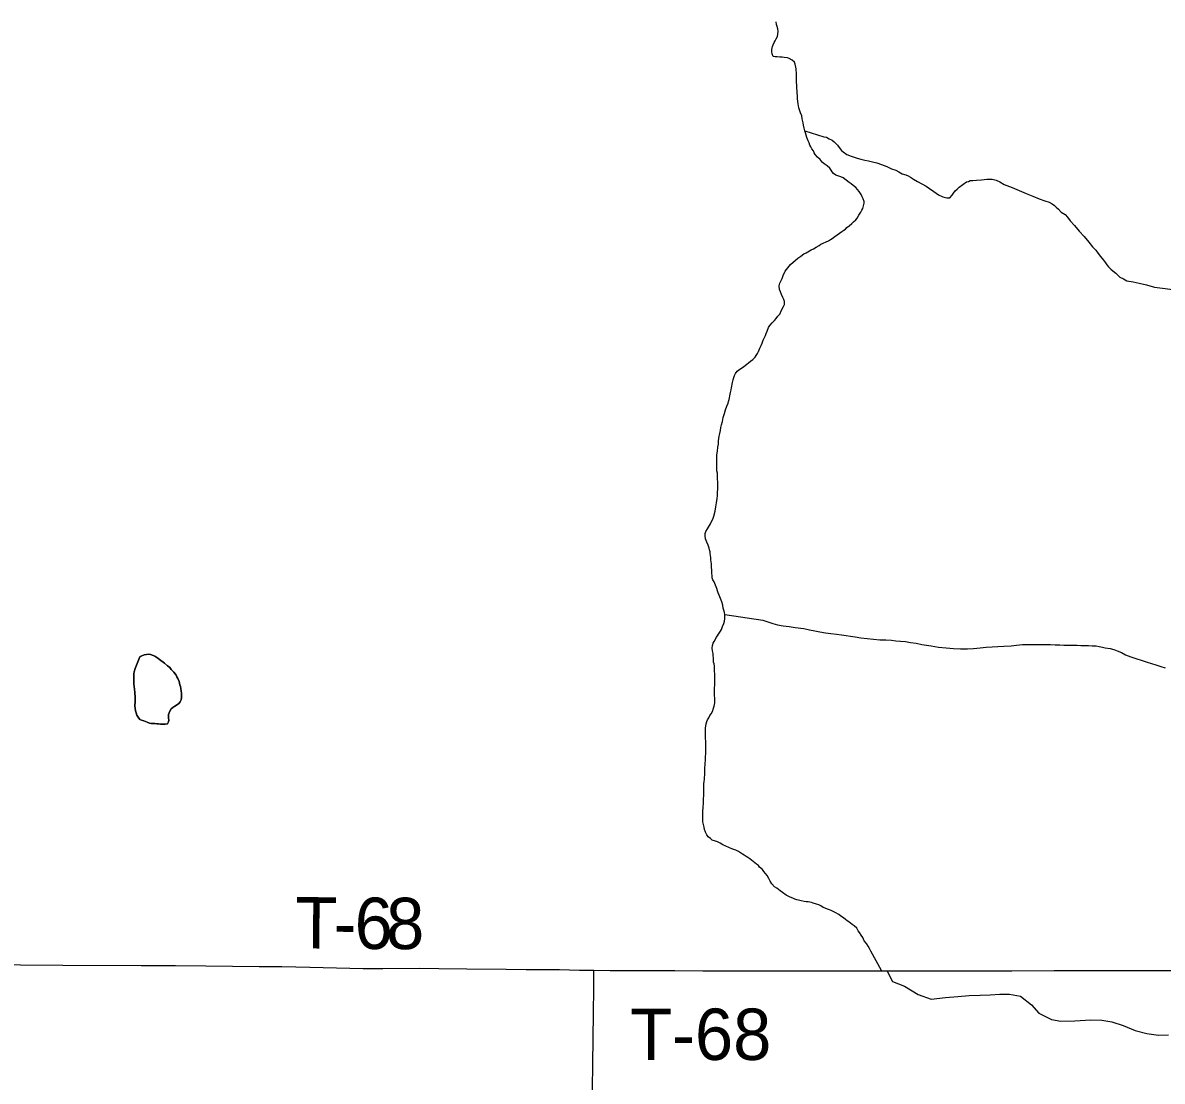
# Model space of a CAD drawing. Extents: x -17 to 88, y -5 to 22.
# Drawn here: x -14.14 to -12.88, y 15.1 to 16.271 of the extents above; entities that cross this region are included whole.
import ezdxf

# ---------------------------------------------------------------- set-up
doc = ezdxf.new("R2010")
doc.units = 0
for name, color, linetype in [('GM_X_City_Street', 7, 'Continuous'), ('GM_X_Minor_Lake', 7, 'Continuous'), ('GM_X_Minor_River', 7, 'Continuous'), ('GM_X_Township_Road', 7, 'Continuous'), ('GM_X_Township_Road_Text', 7, 'Continuous')]:
    doc.layers.add(name, color=color, linetype=linetype)

msp = doc.modelspace()

# ---------------------------------------------------------------- linework, layer by layer
at = {"layer": 'GM_X_City_Street'}
msp.add_lwpolyline([(-14.2652, 15.2295), (-14.2503, 15.2295), (-14.1428, 15.2288), (-14.0962, 15.2284), (-14.0095, 15.2281), (-13.9715, 15.2279), (-13.9378, 15.2277), (-13.8787, 15.227), (-13.8539, 15.2268), (-13.8228, 15.2264), (-13.7638, 15.2248), (-13.7421, 15.2248), (-13.7017, 15.2252), (-13.6799, 15.2248), (-13.6489, 15.2243), (-13.6054, 15.2239), (-13.5836, 15.2237), (-13.5464, 15.2235), (-13.5246, 15.223), (-13.5086, 15.2228)], dxfattribs=at)
at = {"layer": 'GM_X_Minor_Lake'}
for points in [[(-14.0108, 15.5694), (-14.0104, 15.5698), (-14.0093, 15.5702), (-14.0059, 15.5717), (-14.0036, 15.5721), (-14.0009, 15.5725), (-13.999, 15.5721), (-13.996, 15.571), (-13.9941, 15.5702), (-13.9911, 15.5679), (-13.9892, 15.5664), (-13.9835, 15.5626), (-13.9804, 15.5596), (-13.9778, 15.5577), (-13.9763, 15.5554), (-13.9732, 15.5524), (-13.9706, 15.5493), (-13.9698, 15.5474), (-13.9687, 15.5455), (-13.9675, 15.5421), (-13.9668, 15.5387), (-13.966, 15.5368), (-13.9656, 15.5345), (-13.9653, 15.5315), (-13.9649, 15.5292), (-13.9649, 15.5269), (-13.9649, 15.5246), (-13.9653, 15.522), (-13.9664, 15.5197), (-13.9679, 15.5178), (-13.9702, 15.5159), (-13.9721, 15.5151), (-13.9744, 15.5136), (-13.9763, 15.5121), (-13.9778, 15.5094), (-13.9793, 15.5056), (-13.9793, 15.5037), (-13.9793, 15.5015), (-13.9789, 15.4996), (-13.9793, 15.4977), (-13.9804, 15.4954), (-13.9827, 15.495), (-13.9857, 15.495), (-13.988, 15.495), (-13.9903, 15.4954), (-13.9922, 15.4954), (-13.9941, 15.4958), (-13.9964, 15.4958), (-13.9983, 15.4958), (-14.0002, 15.4961), (-14.0028, 15.4973), (-14.0047, 15.498), (-14.0066, 15.4988), (-14.0089, 15.4996), (-14.0108, 15.5003), (-14.0127, 15.5026), (-14.0142, 15.5049), (-14.015, 15.5075), (-14.0157, 15.5098), (-14.0161, 15.5129), (-14.0165, 15.5148), (-14.0161, 15.5204), (-14.0161, 15.5223), (-14.0161, 15.5242), (-14.0161, 15.5265), (-14.0165, 15.5284), (-14.0165, 15.5303), (-14.0169, 15.5334), (-14.0172, 15.5372), (-14.0176, 15.5394), (-14.0176, 15.5417), (-14.0176, 15.5444), (-14.0176, 15.5467), (-14.0176, 15.5489), (-14.0176, 15.5508), (-14.0173, 15.5531), (-14.0161, 15.5565), (-14.0154, 15.5584), (-14.0108, 15.5694)], [(-14.0108, 15.5694), (-14.0154, 15.5584), (-14.0161, 15.5565), (-14.0173, 15.5531), (-14.0176, 15.5508), (-14.0176, 15.5489), (-14.0176, 15.5467), (-14.0176, 15.5444), (-14.0176, 15.5417), (-14.0176, 15.5394), (-14.0172, 15.5372), (-14.0169, 15.5334), (-14.0165, 15.5303), (-14.0165, 15.5284), (-14.0161, 15.5265), (-14.0161, 15.5242), (-14.0161, 15.5223), (-14.0161, 15.5204), (-14.0165, 15.5148), (-14.0161, 15.5129), (-14.0157, 15.5098), (-14.015, 15.5075), (-14.0142, 15.5049), (-14.0127, 15.5026), (-14.0108, 15.5003), (-14.0089, 15.4996), (-14.0066, 15.4988), (-14.0047, 15.498), (-14.0028, 15.4973), (-14.0002, 15.4961), (-13.9983, 15.4958), (-13.9964, 15.4958), (-13.9941, 15.4958), (-13.9922, 15.4954), (-13.9903, 15.4954), (-13.988, 15.495), (-13.9857, 15.495), (-13.9827, 15.495), (-13.9804, 15.4954), (-13.9793, 15.4977)], [(-13.9793, 15.4977), (-13.9789, 15.4996), (-13.9793, 15.5015), (-13.9793, 15.5037), (-13.9793, 15.5056), (-13.9778, 15.5094), (-13.9763, 15.5121), (-13.9744, 15.5136), (-13.9721, 15.5151), (-13.9702, 15.5159), (-13.9679, 15.5178), (-13.9664, 15.5197), (-13.9653, 15.522), (-13.9649, 15.5246), (-13.9649, 15.5269), (-13.9649, 15.5292), (-13.9653, 15.5315), (-13.9656, 15.5345), (-13.966, 15.5368), (-13.9668, 15.5387), (-13.9675, 15.5421), (-13.9687, 15.5455), (-13.9698, 15.5474), (-13.9706, 15.5493), (-13.9732, 15.5524), (-13.9763, 15.5554), (-13.9778, 15.5577), (-13.9804, 15.5596), (-13.9835, 15.5626), (-13.9892, 15.5664), (-13.9911, 15.5679), (-13.9941, 15.5702), (-13.996, 15.571), (-13.999, 15.5721), (-14.0009, 15.5725), (-14.0036, 15.5721), (-14.0059, 15.5717), (-14.0093, 15.5702), (-14.0104, 15.5698), (-14.0108, 15.5694)]]:
    msp.add_lwpolyline(points, dxfattribs=at)
at = {"layer": 'GM_X_Minor_River'}
for points in [[(-13.2942, 16.2322), (-13.298, 16.2326), (-13.3003, 16.2329), (-13.3029, 16.2329), (-13.3056, 16.2333), (-13.3079, 16.2333), (-13.3101, 16.2337), (-13.3113, 16.2364), (-13.3117, 16.2386), (-13.3117, 16.2413), (-13.3109, 16.2447), (-13.3102, 16.2466), (-13.309, 16.2489), (-13.3079, 16.2508), (-13.3067, 16.2531), (-13.3052, 16.2557), (-13.3045, 16.2614), (-13.3048, 16.2641), (-13.3056, 16.2667), (-13.3064, 16.269), (-13.3067, 16.2721)], [(-13.2991, 15.9914), (-13.2968, 15.996), (-13.2941, 15.9998), (-13.2911, 16.0036), (-13.2881, 16.0062), (-13.2858, 16.0078), (-13.2828, 16.0104), (-13.2797, 16.0127), (-13.2763, 16.0154), (-13.2737, 16.0165), (-13.2718, 16.0176), (-13.2699, 16.0188), (-13.268, 16.0199), (-13.2657, 16.0207), (-13.2627, 16.0226), (-13.2592, 16.0245), (-13.2573, 16.026), (-13.249, 16.0298), (-13.2467, 16.0313), (-13.2448, 16.0321), (-13.2418, 16.0343), (-13.2395, 16.0362), (-13.2369, 16.0381), (-13.2342, 16.04), (-13.2319, 16.0416), (-13.23, 16.0427), (-13.2285, 16.0446), (-13.2262, 16.0461), (-13.2232, 16.0488), (-13.2213, 16.0507), (-13.2186, 16.053), (-13.2171, 16.0549), (-13.2152, 16.0579), (-13.213, 16.0613), (-13.2122, 16.0636), (-13.2111, 16.0655), (-13.2103, 16.0685), (-13.2095, 16.0712), (-13.2095, 16.0731), (-13.2107, 16.0761), (-13.2118, 16.0784), (-13.2126, 16.0811), (-13.2149, 16.0841), (-13.2168, 16.0864), (-13.2187, 16.0887), (-13.2217, 16.0909), (-13.224, 16.0928), (-13.2262, 16.0944), (-13.2327, 16.0993), (-13.2354, 16.1004), (-13.2376, 16.1012), (-13.2407, 16.1023), (-13.2433, 16.1042), (-13.2448, 16.1061), (-13.246, 16.108), (-13.2475, 16.1099), (-13.2505, 16.1126), (-13.2536, 16.1149), (-13.2559, 16.1168), (-13.2581, 16.1198), (-13.2612, 16.1224), (-13.2638, 16.1251), (-13.2646, 16.127), (-13.2657, 16.1293), (-13.2672, 16.1316), (-13.2684, 16.1335), (-13.2695, 16.1354), (-13.2703, 16.138), (-13.2714, 16.1403), (-13.2722, 16.1422), (-13.2729, 16.1441), (-13.2737, 16.1467), (-13.2745, 16.149), (-13.2752, 16.1513), (-13.276, 16.1543), (-13.2767, 16.1578), (-13.2771, 16.1604), (-13.2779, 16.1646), (-13.2786, 16.168), (-13.2798, 16.1714), (-13.2809, 16.1745), (-13.2817, 16.1767), (-13.2821, 16.179), (-13.2824, 16.1813), (-13.2828, 16.184), (-13.2832, 16.187), (-13.2832, 16.1897), (-13.2836, 16.1938), (-13.2843, 16.2067), (-13.2843, 16.2094), (-13.2843, 16.2121), (-13.2843, 16.214), (-13.2843, 16.2159), (-13.2847, 16.2181), (-13.2847, 16.22), (-13.2851, 16.2219), (-13.2859, 16.225), (-13.2866, 16.2272), (-13.2893, 16.2295), (-13.2923, 16.2314), (-13.2942, 16.2322)], [(-13.2752, 16.1513), (-13.254, 16.1449), (-13.2513, 16.1445), (-13.2483, 16.1426), (-13.2449, 16.1411), (-13.2426, 16.1392), (-13.2407, 16.1373), (-13.2388, 16.1354), (-13.2361, 16.1316), (-13.2346, 16.1297), (-13.2327, 16.1281), (-13.2285, 16.1251), (-13.224, 16.1232), (-13.2171, 16.1213), (-13.213, 16.1202), (-13.2088, 16.119), (-13.2046, 16.1183), (-13.2001, 16.1171), (-13.1955, 16.116), (-13.1902, 16.1141), (-13.1845, 16.1118), (-13.1792, 16.1095), (-13.1746, 16.108), (-13.1712, 16.1061), (-13.1674, 16.1039), (-13.1633, 16.1027), (-13.1606, 16.1016), (-13.1583, 16.1001), (-13.1549, 16.0978), (-13.1504, 16.0955), (-13.1458, 16.0928), (-13.1409, 16.0902), (-13.1371, 16.0875), (-13.1325, 16.0841), (-13.1272, 16.0807), (-13.1223, 16.0784), (-13.1181, 16.0773), (-13.1147, 16.0773), (-13.112, 16.0803), (-13.1105, 16.0826), (-13.1086, 16.0849), (-13.1067, 16.0868), (-13.1044, 16.0891), (-13.0961, 16.0948), (-13.0942, 16.0955), (-13.0923, 16.0963), (-13.0893, 16.0963), (-13.0851, 16.0967), (-13.0798, 16.097), (-13.0737, 16.0978), (-13.068, 16.0978), (-13.0635, 16.0967), (-13.0593, 16.0948), (-13.0544, 16.0921), (-13.0456, 16.0887), (-13.038, 16.0853), (-13.0304, 16.0822), (-13.0229, 16.0792), (-13.016, 16.0762), (-13.0096, 16.0739), (-13.0046, 16.0724), (-13.0016, 16.0705), (-12.9989, 16.0689), (-12.997, 16.067), (-12.9944, 16.0648), (-12.9914, 16.0614), (-12.9872, 16.0587), (-12.9845, 16.056), (-12.9815, 16.0519), (-12.9769, 16.0465), (-12.9716, 16.0405), (-12.9659, 16.0344), (-12.961, 16.0283), (-12.9568, 16.023), (-12.953, 16.0192), (-12.9504, 16.0158), (-12.9481, 16.0124), (-12.9447, 16.0082), (-12.9424, 16.0055), (-12.9409, 16.0033), (-12.939, 16.001), (-12.9367, 15.9983), (-12.9344, 15.9964), (-12.931, 15.9938), (-12.9291, 15.9919), (-12.9265, 15.9896), (-12.9227, 15.9877), (-12.9189, 15.9854), (-12.912, 15.9843), (-12.9052, 15.9828), (-12.8972, 15.9809), (-12.8881, 15.9786), (-12.8619, 15.9752)], [(-13.3844, 15.6983), (-13.3851, 15.7002), (-13.3855, 15.7032), (-13.3855, 15.7059), (-13.3848, 15.7081), (-13.3829, 15.7112), (-13.3817, 15.7131), (-13.3794, 15.7165), (-13.3783, 15.7191), (-13.3768, 15.7218), (-13.3757, 15.7252), (-13.3745, 15.7305), (-13.3734, 15.7355), (-13.373, 15.74), (-13.3722, 15.7446), (-13.3719, 15.7476), (-13.3719, 15.7495), (-13.3719, 15.7522), (-13.3715, 15.7545), (-13.3715, 15.7575), (-13.3715, 15.7605), (-13.3715, 15.7632), (-13.3719, 15.7662), (-13.3719, 15.77), (-13.3719, 15.7727), (-13.3723, 15.7753), (-13.3723, 15.778), (-13.3723, 15.7883), (-13.3723, 15.7928), (-13.3719, 15.797), (-13.3715, 15.8015), (-13.3707, 15.8046), (-13.3707, 15.8084), (-13.3704, 15.811), (-13.37, 15.8137), (-13.3692, 15.8167), (-13.3685, 15.8198), (-13.3681, 15.8232), (-13.3673, 15.8262), (-13.3662, 15.83), (-13.3654, 15.8342), (-13.3639, 15.8388), (-13.3628, 15.8429), (-13.3613, 15.8467), (-13.3601, 15.8502), (-13.3594, 15.8521), (-13.359, 15.854), (-13.3586, 15.8562), (-13.3582, 15.8581), (-13.3579, 15.86), (-13.3575, 15.8619), (-13.3567, 15.865), (-13.3563, 15.8669), (-13.356, 15.8688), (-13.3556, 15.871), (-13.3552, 15.8729), (-13.3544, 15.876), (-13.3537, 15.8786), (-13.3529, 15.8809), (-13.3518, 15.8828), (-13.3499, 15.8855), (-13.3472, 15.8878), (-13.3453, 15.8889), (-13.3427, 15.8908), (-13.3393, 15.8931), (-13.3374, 15.8946), (-13.3351, 15.8965), (-13.3328, 15.8984), (-13.3302, 15.901), (-13.329, 15.9029), (-13.3275, 15.9052), (-13.3264, 15.9071), (-13.3249, 15.9109), (-13.3233, 15.914), (-13.3222, 15.9166), (-13.3211, 15.9197), (-13.3199, 15.9227), (-13.3188, 15.925), (-13.318, 15.9273), (-13.3169, 15.9299), (-13.3154, 15.9337), (-13.3139, 15.936), (-13.3112, 15.939), (-13.3085, 15.9417), (-13.307, 15.9436), (-13.3048, 15.9462), (-13.3029, 15.9485), (-13.301, 15.9531), (-13.2987, 15.9569), (-13.2975, 15.9592), (-13.2975, 15.9626), (-13.2983, 15.9648), (-13.2994, 15.9671), (-13.301, 15.9705), (-13.3021, 15.9732), (-13.3032, 15.9759), (-13.3036, 15.98), (-13.3029, 15.9827), (-13.3017, 15.985), (-13.3002, 15.988), (-13.2991, 15.9914)], [(-13.387, 15.4157), (-13.387, 15.4195), (-13.387, 15.4233), (-13.387, 15.4271), (-13.387, 15.429), (-13.3866, 15.4317), (-13.3862, 15.434), (-13.3862, 15.4362), (-13.3858, 15.4389), (-13.3858, 15.4419), (-13.3858, 15.4461), (-13.3854, 15.451), (-13.3851, 15.4556), (-13.3851, 15.4594), (-13.3847, 15.4621), (-13.3847, 15.4681), (-13.3847, 15.47), (-13.3847, 15.4719), (-13.3847, 15.4742), (-13.3847, 15.4761), (-13.3851, 15.4792), (-13.3851, 15.4822), (-13.3851, 15.486), (-13.3851, 15.489), (-13.3851, 15.4909), (-13.3847, 15.4928), (-13.3843, 15.4955), (-13.3836, 15.4978), (-13.3828, 15.5), (-13.3813, 15.5019), (-13.3801, 15.5046), (-13.3786, 15.5065), (-13.3771, 15.5092), (-13.376, 15.5129), (-13.3756, 15.5148), (-13.3752, 15.5167), (-13.3748, 15.5186), (-13.3748, 15.5236), (-13.3752, 15.527), (-13.3752, 15.5308), (-13.3752, 15.5346), (-13.3748, 15.5388), (-13.3748, 15.5422), (-13.3748, 15.546), (-13.3748, 15.5483), (-13.3748, 15.5502), (-13.3752, 15.554), (-13.3752, 15.5566), (-13.3752, 15.5593), (-13.3756, 15.5619), (-13.376, 15.5638), (-13.376, 15.568), (-13.3764, 15.571), (-13.3767, 15.5733), (-13.3771, 15.576), (-13.3775, 15.579), (-13.3771, 15.5821), (-13.3764, 15.5847), (-13.3756, 15.5866), (-13.3741, 15.5889), (-13.3733, 15.5908), (-13.3718, 15.5927), (-13.3707, 15.5946), (-13.3684, 15.598), (-13.3673, 15.5999), (-13.3661, 15.6029), (-13.3646, 15.6064), (-13.3639, 15.609), (-13.3635, 15.6117), (-13.3635, 15.614), (-13.3635, 15.6162), (-13.3639, 15.6185), (-13.3646, 15.6212), (-13.3654, 15.6235), (-13.3658, 15.6265), (-13.3669, 15.6303), (-13.3684, 15.6341), (-13.3699, 15.6379), (-13.3711, 15.6402), (-13.3718, 15.6424), (-13.3726, 15.6451), (-13.3741, 15.6489), (-13.3756, 15.6523), (-13.3768, 15.6546), (-13.3775, 15.6569), (-13.3779, 15.6641), (-13.3779, 15.666), (-13.3783, 15.6679), (-13.3783, 15.6702), (-13.3783, 15.6724), (-13.3787, 15.6747), (-13.3791, 15.677), (-13.3791, 15.6793), (-13.3794, 15.6816), (-13.3798, 15.6838), (-13.3798, 15.6857), (-13.3806, 15.688), (-13.381, 15.6899), (-13.3821, 15.6929), (-13.3836, 15.6964), (-13.3844, 15.6983)], [(-13.3635, 15.6162), (-13.3214, 15.6102), (-13.316, 15.6083), (-13.3107, 15.6064), (-13.3054, 15.6049), (-13.299, 15.6037), (-13.2925, 15.603), (-13.2857, 15.6018), (-13.2762, 15.6007), (-13.2698, 15.5995), (-13.2641, 15.5984), (-13.2584, 15.5973), (-13.2523, 15.5961), (-13.2462, 15.5954), (-13.2402, 15.5946), (-13.2345, 15.5939), (-13.2295, 15.5931), (-13.2246, 15.5923), (-13.2193, 15.5916), (-13.2132, 15.5904), (-13.192, 15.5885), (-13.1855, 15.5885), (-13.1794, 15.5878), (-13.1745, 15.5874), (-13.1692, 15.5867), (-13.1639, 15.5863), (-13.1582, 15.5855), (-13.1521, 15.5848), (-13.1457, 15.5832), (-13.1354, 15.5817), (-13.1271, 15.5802), (-13.1187, 15.5794), (-13.1108, 15.5787), (-13.1028, 15.5783), (-13.0952, 15.5783), (-13.0884, 15.5787), (-13.0812, 15.5794), (-13.0743, 15.5802), (-13.0679, 15.5806), (-13.0614, 15.581), (-13.055, 15.5814), (-13.047, 15.5817), (-13.0409, 15.5825), (-13.0341, 15.5833), (-13.0277, 15.5833), (-13.0212, 15.5833), (-13.0151, 15.5833), (-13.0091, 15.5833), (-13.0034, 15.5833), (-12.9981, 15.5829), (-12.9931, 15.5829), (-12.9886, 15.5825), (-12.984, 15.5825), (-12.981, 15.5825), (-12.9776, 15.5825), (-12.9738, 15.5825), (-12.9696, 15.5821), (-12.9654, 15.5821), (-12.9613, 15.5821), (-12.9571, 15.5817), (-12.9529, 15.5817), (-12.9495, 15.581), (-12.9457, 15.5802), (-12.9427, 15.5795), (-12.9373, 15.5787), (-12.9332, 15.5776), (-12.9294, 15.5761), (-12.9248, 15.5742), (-12.9203, 15.5719), (-12.9146, 15.5696), (-12.8964, 15.5635), (-12.8914, 15.562), (-12.8869, 15.5605), (-12.8812, 15.559), (-12.8763, 15.5575)], [(-13.1902, 15.2226), (-13.2021, 15.2441), (-13.2036, 15.2468), (-13.2051, 15.2494), (-13.2067, 15.2525), (-13.2093, 15.2555), (-13.2108, 15.2589), (-13.2127, 15.2616), (-13.2146, 15.2646), (-13.2162, 15.2665), (-13.2177, 15.2692), (-13.2207, 15.2718), (-13.2226, 15.2734), (-13.2245, 15.2749), (-13.2264, 15.2764), (-13.2283, 15.2775), (-13.2302, 15.279), (-13.2325, 15.2809), (-13.2351, 15.2828), (-13.2374, 15.2844), (-13.2416, 15.2866), (-13.2458, 15.2889), (-13.2477, 15.2897), (-13.2499, 15.2904), (-13.2526, 15.2916), (-13.2549, 15.2923), (-13.2575, 15.2939), (-13.2598, 15.295), (-13.2621, 15.2961), (-13.2659, 15.2969), (-13.2678, 15.2977), (-13.2697, 15.298), (-13.2716, 15.2984), (-13.2738, 15.2984), (-13.2757, 15.2988), (-13.2792, 15.2995), (-13.2822, 15.3003), (-13.2841, 15.3007), (-13.286, 15.3014), (-13.2883, 15.3026), (-13.2913, 15.3037), (-13.2936, 15.3049), (-13.2959, 15.306), (-13.3, 15.309), (-13.3023, 15.3106), (-13.3042, 15.3121), (-13.3061, 15.3136), (-13.3088, 15.3151), (-13.3118, 15.3185), (-13.3133, 15.3212), (-13.3148, 15.3242), (-13.3167, 15.3276), (-13.3186, 15.3299), (-13.3205, 15.3322), (-13.322, 15.3341), (-13.3251, 15.3368), (-13.3262, 15.3387), (-13.3285, 15.3402), (-13.3304, 15.3417), (-13.3323, 15.3432), (-13.3342, 15.3447), (-13.3361, 15.3459), (-13.338, 15.3474), (-13.3399, 15.3485), (-13.3422, 15.35), (-13.3441, 15.3512), (-13.3463, 15.3527), (-13.3486, 15.3542), (-13.3516, 15.3557), (-13.3535, 15.3565), (-13.3558, 15.3573), (-13.3626, 15.3599), (-13.3657, 15.3614), (-13.3687, 15.3633), (-13.3718, 15.3648), (-13.374, 15.3656), (-13.3775, 15.3667), (-13.3793, 15.3686), (-13.382, 15.3705), (-13.3835, 15.3728), (-13.385, 15.3755), (-13.3862, 15.3785), (-13.3866, 15.3812), (-13.3873, 15.3842), (-13.3881, 15.3869), (-13.3881, 15.3888), (-13.3881, 15.3926), (-13.3881, 15.3948), (-13.3881, 15.3967), (-13.3881, 15.3998), (-13.3877, 15.4017), (-13.3877, 15.4043), (-13.3873, 15.4066), (-13.3873, 15.4085), (-13.3873, 15.4104), (-13.3873, 15.4127), (-13.387, 15.4157)], [(-13.1842, 15.2219), (-13.1782, 15.2102), (-13.165, 15.2051), (-13.1499, 15.1959), (-13.1352, 15.1908), (-13.1193, 15.1925), (-13.106, 15.1939), (-13.0934, 15.1949), (-13.0813, 15.1952), (-13.0699, 15.1958), (-13.0593, 15.1965), (-13.0487, 15.1964), (-13.0366, 15.194), (-13.0245, 15.1847), (-13.0163, 15.1752), (-13.0023, 15.1682), (-12.9917, 15.1666), (-12.9762, 15.1668), (-12.9587, 15.1681), (-12.9466, 15.1676), (-12.9356, 15.1656), (-12.9228, 15.1617), (-12.9095, 15.1562), (-12.8967, 15.1527), (-12.8838, 15.151), (-12.8728, 15.1513)]]:
    msp.add_lwpolyline(points, dxfattribs=at)
at = {"layer": 'GM_X_Township_Road'}
for points in [[(-14.2652, 15.2295), (-14.2503, 15.2295), (-14.1428, 15.2288), (-14.0962, 15.2284), (-14.0095, 15.2281), (-13.9715, 15.2279), (-13.9378, 15.2277), (-13.8787, 15.227), (-13.8539, 15.2268), (-13.8228, 15.2264), (-13.7638, 15.2248), (-13.7421, 15.2248), (-13.7017, 15.2252), (-13.6799, 15.2248), (-13.6489, 15.2243), (-13.6054, 15.2239), (-13.5836, 15.2237), (-13.5464, 15.2235), (-13.5246, 15.223), (-13.5086, 15.2228)], [(-13.5105, 15.0632), (-13.5095, 15.1192), (-13.5088, 15.1751), (-13.5084, 15.2031), (-13.5086, 15.2228)], [(-13.5086, 15.2228), (-13.4905, 15.2226), (-13.4688, 15.2225), (-13.4191, 15.2224), (-13.388, 15.2223), (-13.36, 15.2223), (-13.3072, 15.2222), (-13.2574, 15.2223), (-13.2565, 15.2223)], [(-13.5086, 15.2228), (-13.4905, 15.2226), (-13.4688, 15.2225), (-13.4191, 15.2224), (-13.388, 15.2223), (-13.36, 15.2223), (-13.3072, 15.2222), (-13.2574, 15.2223), (-13.2565, 15.2223)], [(-13.2565, 15.2223), (-13.1804, 15.2221), (-13.1237, 15.2221), (-13.0937, 15.2221), (-13.046, 15.2223), (-12.9994, 15.2224), (-12.9652, 15.2224), (-12.9431, 15.2226), (-12.9031, 15.2225), (-12.8191, 15.2224)], [(-13.2565, 15.2223), (-13.1804, 15.2221), (-13.1237, 15.2221), (-13.0937, 15.2221), (-13.046, 15.2223), (-12.9994, 15.2224), (-12.9652, 15.2224), (-12.9431, 15.2226), (-12.9031, 15.2225), (-12.8191, 15.2224)]]:
    msp.add_lwpolyline(points, dxfattribs=at)

# ---------------------------------------------------------------- texts
at = {"layer": 'GM_X_Township_Road_Text'}
for s, height, rotation, p in [('T', 0.0568, 359.4709, (-13.8391, 15.2471)), ('6', 0.0568, 359.6244, (-13.7734, 15.2465)), ('8', 0.0568, 359.7363, (-13.7385, 15.2463)), ('-', 0.0568, 359.5394, (-13.7966, 15.2467)), ('T-68', 0.05682, 0, (-13.4684, 15.1236))]:
    msp.add_text(s, height=height, rotation=rotation, dxfattribs=at).set_placement(p)

doc.saveas('drawing.dxf')
